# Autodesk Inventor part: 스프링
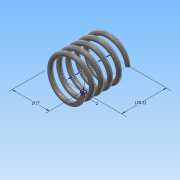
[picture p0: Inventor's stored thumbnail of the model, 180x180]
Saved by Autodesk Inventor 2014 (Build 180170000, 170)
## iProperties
Created: 2016-01
Part Number: 스프링
Material: 강철, 탄소
Document SubType Name: Modeling
Designer: Administrator
Density: 7.87 g/cm^3
Appearance: 반연마
Mass: 6.46669 g
Surface Area: 16.7182 cm^2
Volume: 0.821689 cm^3
Author: Administrator
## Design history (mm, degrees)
sketch "스케치1"
  geometry: L1 (0, 0)-(8.5, 0); L2 (8.5, 0)-(8.5, 20.5); L3 (8.5, 20.5)-(0, 20.5); L4 (0, 20.5)-(0, 0); C1 r 1 at (8.5, 0)
  constraints: 8 end point, 2 parallel, 1 centre point, 1 coincident, 1 horizontal, 1 perpendicular
  dimensions: "d0" = 20.5 distance of L1.end L2.end (derived); "d1" = 17 diameter of L2 L4; "d2" = 2 diameter of C1
feature "코일1" sketch "스케치1" pitch "d3" = 10; turns "d5" = 5; dims "d4" = 20.5 (= d0), "d6" = 0, angle "d7" = 90 deg, angle "d8" = 90 deg, "d9" = 0, "d10" = 0
node "작업 평면2"
  node "작업 평면1"
sketch "스케치2"
  geometry: L1 (-9.5, 0)-(-7.5, 0) reference; 1 further point
  constraints: 1 horizontal alignment
extrude "돌출1" cut sketch "스케치2" distance "d13" = 10; taper "d14" = 0 deg
sketch "스케치3"
  geometry: L1 (-7.5, 0)-(-9.5, 0) reference; 1 further point
  constraints: 1 horizontal alignment
extrude "돌출2" cut sketch "스케치3" distance "d15" = 10; taper "d16" = 0 deg
node "솔리드1"
node "절단 모서리 투영1"
node "절단 모서리 투영2"
other parameters: "d11" = 0, "d12" = 20.5 (= d0)
